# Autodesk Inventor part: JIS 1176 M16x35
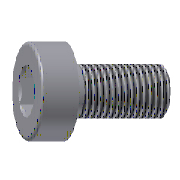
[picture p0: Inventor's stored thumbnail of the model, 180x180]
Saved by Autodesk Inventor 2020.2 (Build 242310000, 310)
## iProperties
Manager: www.cadconsulting.pl
Company: Fabian Stasiak CAD Consulting
Created: 2014-02
Part Number: JIS 1176 M16x35
Material: Stal, miękka
Description: Cylinder Head Cap Screw
Document SubType Name: Modeling
Designer: F.Stasiak
Standard Revision: 1
Language: pl-PL
Size Designation: M16x35
Categories: <MemberInstance><Categories><Category DisplayName="Forma wtryskowa" InternalName="349578f2-f4d4-4954-8c09-8e99297a61c0" Mnemonic="MOLD"><Category DisplayName="C
Mass: 0.133121 g
Surface Area: 2.01441 cm^2
Volume: 0.133121 cm^3
Density: 7.85 g/cm^3
Appearance: Częściowo polerowana
Catalog Web Link: www.expertbooks.pl
IsCustomPart: 0
Author: F.Stasiak
Subject: Zbiór ćwiczeń. Autodesk Inventor 2020. Kurs Professional
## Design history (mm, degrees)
sketch "Sketch1"
  geometry: L1 (0, -45.2)-(0, 26.2) reference; L2 (8.083, 16)-(12, 16); L3 (12, 16)-(12, 0); L4 (12, 0)-(8, 0); L5 (8, 0)-(8, -35); L6 (8, -35)-(0, -35); L7 (0, 3.794)-(0, -35); L8 (0, 3.794)-(7, 8); L9 (7, 8)-(7, 14.917); L10 (7, 14.917)-(8.083, 16); 1 further point
  constraints: 18 end point, 4 vertical, 3 horizontal, 2 point on line
  dimensions: "d0" = 24 diameter of L3 L1 (= dk); "d1" = 16 distance between parallel lines of L4 L2 (= k); "d2" = 16 diameter of L5 L1 (= d); "d3" = 35 distance between parallel lines of L6 L4 (= L); "d4" = 59 deg angle of L1 L8; "d5" = 45 deg angle of L1 L10; "d6" = 14 diameter of L9 L1 (= sw); "d7" = 16.16581 diameter of L2.start L1 (= 1.1547 x sw); "d8" = 8 distance from line of L8.end L2 (= t)
revolve "Revolution1" sketch "Sketch1" stored, may be unused: angle "d44" = 90 deg
sketch "Sketch2"
  geometry: L1 (0, 8.083)-(7, 4.041); L2 (7, 4.041)-(7, -4.041); L3 (7, -4.041)-(0, -8.083); L4 (0, -8.083)-(-7, -4.041); L5 (-7, -4.041)-(-7, 4.041); L6 (-7, 4.041)-(0, 8.083); 3 further points
  constraints: 12 end point, 2 vertical alignment, 1 coincident, 14 other
extrude "Extrusion1" cut sketch "Sketch2" taper "d9" = 0 deg; stored distance "d45" = 10
thread "Thread1" dims "d10" = 30 (= b), "d11" = 0
chamfer "Chamfer1" distance "d12" = 1 (= 0.5 x P); stored, may be unused: second distance "d50" = 2, angle "d51" = 45 deg
fillet "Fillet1" dims "d13" = 1 (= 0.5 x P)
body "Solid1"
other parameters: "d" = 16 [user parameter; used in 1 equation term], "L" = 35 [user parameter; used in 1 equation term], "dk" = 24 [user parameter; used in 1 equation term], "b" = 30 [user parameter; used in 1 equation term], "k" = 16 [user parameter; used in 1 equation term], "sw" = 14 [user parameter; used in 2 equation terms], "t" = 8 [user parameter; used in 1 equation term], "P" = 2 [user parameter; used in 2 equation terms], "d14" = 0, "d15" = 0, "d55" = 0
